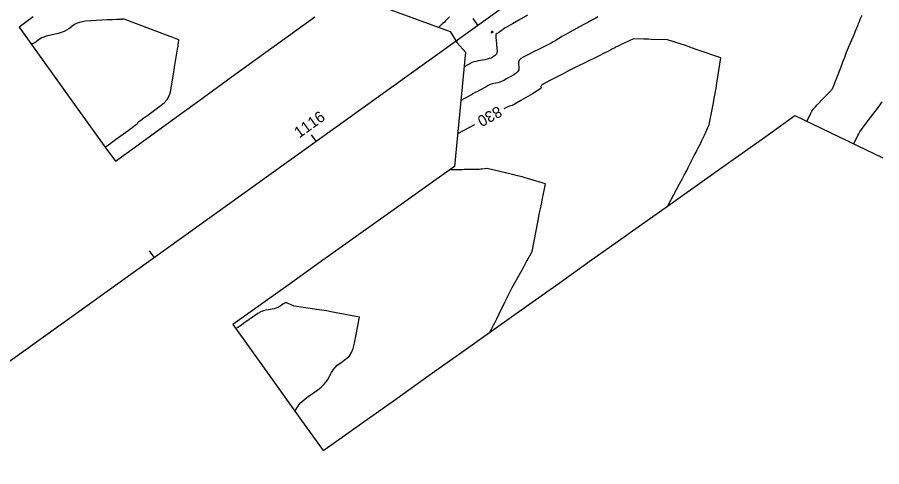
# Model space of a CAD drawing. Extents: x 2079879 to 2092887, y 778083 to 784051.
# Drawn here: x 2083587.5 to 2083804.7, y 780682.1 to 780794.9 of the extents above; entities that cross this region are included whole.
import ezdxf

# ---------------------------------------------------------------- set-up
doc = ezdxf.new("R2010")
doc.units = 0
for name, color, linetype in [('DT_X_Contour_Major', 7, 'Continuous'), ('DT_X_Contour_Minor', 7, 'Continuous'), ('DT_X_TIN_Hull', 7, 'Continuous'), ('GE_X_CL_20', 7, 'Continuous')]:
    doc.layers.add(name, color=color, linetype=linetype)

msp = doc.modelspace()

# ---------------------------------------------------------------- linework, layer by layer
at = {"layer": 'DT_X_Contour_Major'}
for points in [[(2083750.94, 780747.61), (2083753.91, 780753.14), (2083754.53, 780754.28), (2083755.09, 780755.35), (2083755.61, 780756.34), (2083756.08, 780757.25), (2083757.26, 780759.59), (2083757.68, 780760.41), (2083758.04, 780761.12), (2083758.35, 780761.72), (2083758.61, 780762.21), (2083759.21, 780763.39), (2083759.44, 780763.84), (2083759.68, 780764.33), (2083759.93, 780764.84), (2083760.18, 780765.39), (2083761.37, 780768), (2083762.4, 780773.44), (2083762.62, 780774.62), (2083762.84, 780775.86), (2083763.06, 780777.13), (2083763.28, 780778.45), (2083764.3, 780784.73), (2083758.33, 780786.8), (2083757.12, 780787.22), (2083756.05, 780787.59), (2083755.11, 780787.91), (2083754.3, 780788.17), (2083750.87, 780789.29), (2083746.79, 780789.41), (2083746.14, 780789.43), (2083745.52, 780789.45), (2083744.94, 780789.47), (2083742.35, 780789.55), (2083739.07, 780788.01), (2083738.45, 780787.71), (2083738, 780787.5), (2083737.72, 780787.37), (2083737.61, 780787.32), (2083736.93, 780786.95), (2083736.82, 780786.89), (2083736.73, 780786.84), (2083736.68, 780786.81), (2083736.64, 780786.79), (2083736.59, 780786.75), (2083736.4, 780786.65), (2083735.85, 780786.37), (2083734.95, 780785.93), (2083733.7, 780785.31), (2083729.91, 780783.42), (2083728.51, 780782.73), (2083727.17, 780782.06), (2083725.88, 780781.41), (2083724.65, 780780.79), (2083721.45, 780779.15), (2083720.4, 780778.6), (2083719.66, 780778.16), (2083719.21, 780777.84), (2083719.08, 780777.64), (2083719.12, 780777.26), (2083718.99, 780777.05), (2083718.59, 780776.73), (2083717.91, 780776.28), (2083716.96, 780775.72), (2083714.04, 780774.05), (2083713.06, 780773.49), (2083712.32, 780773.09), (2083711.82, 780772.84), (2083711.55, 780772.74), (2083711.16, 780772.66), (2083710.9, 780772.57), (2083710.43, 780772.34), (2083709.75, 780771.99), (2083709.74, 780771.98)], [(2083702.38, 780767.95), (2083702.37, 780767.94), (2083698.15, 780765.68)]]:
    msp.add_lwpolyline(points, dxfattribs=at)
at = {"layer": 'DT_X_Contour_Minor'}
for points in [[(2083609.68, 780762.3), (2083609.8, 780762.48), (2083609.97, 780762.62), (2083610.43, 780762.96), (2083611.18, 780763.5), (2083612.22, 780764.25), (2083615.37, 780766.52), (2083616.42, 780767.28), (2083617.17, 780767.84), (2083617.64, 780768.21), (2083617.82, 780768.38), (2083617.93, 780768.6), (2083618.11, 780768.77), (2083618.56, 780769.13), (2083619.3, 780769.68), (2083620.32, 780770.41), (2083623.39, 780772.63), (2083624.42, 780773.47), (2083625.2, 780774.35), (2083625.73, 780775.25), (2083626.01, 780776.19), (2083626.43, 780778.73), (2083626.59, 780779.7), (2083626.75, 780780.72), (2083626.93, 780781.79), (2083627.12, 780782.91), (2083627.62, 780785.94), (2083627.79, 780786.96), (2083627.92, 780787.73), (2083628, 780788.25), (2083628.05, 780788.53), (2083628.15, 780789.25), (2083627.43, 780789.56), (2083627.06, 780789.71), (2083626.24, 780790.03), (2083624.99, 780790.5), (2083623.29, 780791.14), (2083614.37, 780794.51), (2083613.88, 780794.45), (2083613.78, 780794.44), (2083613.69, 780794.44), (2083613.61, 780794.43), (2083613.53, 780794.43), (2083613.34, 780794.43), (2083613.08, 780794.42), (2083612.46, 780794.38), (2083611.48, 780794.34), (2083610.13, 780794.27), (2083606.06, 780794.06), (2083604.66, 780793.94), (2083603.5, 780793.74), (2083602.59, 780793.47), (2083601.93, 780793.11), (2083600.51, 780792.06), (2083599.93, 780791.7), (2083599.29, 780791.38), (2083598.58, 780791.12), (2083597.79, 780790.9), (2083595.6, 780790.4), (2083594.84, 780790.21), (2083594.2, 780790), (2083593.69, 780789.79), (2083593.31, 780789.56), (2083592.46, 780788.93), (2083592.17, 780788.72), (2083591.92, 780788.57), (2083591.72, 780788.46), (2083591.58, 780788.41), (2083591, 780788.29)], [(2083696.1, 780795.09), (2083695.64, 780794.6), (2083695.27, 780794.22), (2083695, 780793.94), (2083694.82, 780793.76), (2083694.47, 780793.43), (2083694.34, 780793.31), (2083694.21, 780793.19), (2083694.09, 780793.07), (2083693.97, 780792.96), (2083693.42, 780792.44)], [(2083733.38, 780795.03), (2083732.72, 780794.67), (2083732.34, 780794.47), (2083731.71, 780794.13), (2083730.83, 780793.64), (2083729.69, 780793.03), (2083726.32, 780791.19), (2083725.19, 780790.57), (2083724.33, 780790.09), (2083723.73, 780789.74), (2083723.39, 780789.53), (2083722.86, 780789.15), (2083722.59, 780788.98), (2083722.19, 780788.75), (2083721.65, 780788.47), (2083720.98, 780788.13), (2083719, 780787.15), (2083718.27, 780786.79), (2083717.58, 780786.44), (2083716.91, 780786.1), (2083716.27, 780785.78), (2083714.6, 780784.93), (2083714.06, 780784.59), (2083713.69, 780784.23), (2083713.48, 780783.83), (2083713.44, 780783.4), (2083713.57, 780782.21), (2083713.52, 780781.77), (2083713.29, 780781.34), (2083712.87, 780780.93), (2083712.27, 780780.52), (2083710.42, 780779.46), (2083709.76, 780779.11), (2083709.18, 780778.83), (2083708.68, 780778.64), (2083708.26, 780778.52), (2083707.24, 780778.33), (2083706.83, 780778.22), (2083706.37, 780778.06), (2083705.85, 780777.83), (2083705.29, 780777.53), (2083703.71, 780776.66), (2083703.13, 780776.34), (2083702.56, 780776.03), (2083702.01, 780775.72), (2083701.46, 780775.43), (2083698.98, 780774.1)], [(2083715.72, 780795.44), (2083713.56, 780794.26), (2083711.92, 780793.34), (2083710.78, 780792.67), (2083710.14, 780792.27), (2083709.13, 780791.55), (2083708.79, 780791.31), (2083708.53, 780791.13), (2083708.35, 780791.01), (2083708.25, 780790.95), (2083708.1, 780790.87), (2083708.04, 780790.84), (2083707.99, 780790.82), (2083707.93, 780790.79), (2083707.88, 780790.76), (2083707.76, 780790.7), (2083707.72, 780790.58), (2083707.72, 780790.29), (2083707.75, 780789.81), (2083707.81, 780789.15), (2083708.02, 780787.16), (2083708.05, 780786.49), (2083707.98, 780785.96), (2083707.83, 780785.57), (2083707.58, 780785.33), (2083706.8, 780784.88), (2083706.46, 780784.72), (2083706.05, 780784.57), (2083705.55, 780784.43), (2083704.97, 780784.31), (2083703.32, 780784), (2083702.76, 780783.88), (2083702.3, 780783.77), (2083701.96, 780783.67), (2083701.72, 780783.56), (2083701.24, 780783.3), (2083701.07, 780783.2), (2083700.89, 780783.11), (2083700.72, 780783.01), (2083700.56, 780782.93), (2083699.8, 780782.52)], [(2083785.88, 780768.82), (2083786.88, 780770.9), (2083787.14, 780771.36), (2083787.49, 780771.86), (2083787.93, 780772.4), (2083788.47, 780772.98), (2083790.02, 780774.57), (2083790.55, 780775.12), (2083790.98, 780775.56), (2083791.31, 780775.89), (2083791.53, 780776.12), (2083792.34, 780776.96), (2083794.46, 780782.55), (2083794.92, 780783.75), (2083795.4, 780784.95), (2083795.88, 780786.16), (2083796.38, 780787.37), (2083797.73, 780790.59), (2083798.18, 780791.68), (2083798.52, 780792.5), (2083798.76, 780793.07), (2083798.88, 780793.39), (2083799.08, 780793.89), (2083799.15, 780794.07), (2083799.23, 780794.26), (2083799.3, 780794.44), (2083799.38, 780794.63), (2083799.75, 780795.49)], [(2083706.89, 780791.1), (2083706.85, 780791.08), (2083706.82, 780791.06), (2083706.79, 780791.04), (2083706.76, 780791.02), (2083706.63, 780790.94), (2083706.67, 780791.01), (2083706.68, 780791.02), (2083706.68, 780791.05), (2083706.69, 780791.08), (2083706.7, 780791.12), (2083706.73, 780791.32), (2083706.74, 780791.38), (2083706.76, 780791.5), (2083706.81, 780791.5), (2083706.82, 780791.5), (2083706.84, 780791.48), (2083706.87, 780791.45), (2083706.9, 780791.41), (2083706.99, 780791.29), (2083707.02, 780791.25), (2083707.02, 780791.21), (2083707.01, 780791.18), (2083706.99, 780791.16), (2083706.89, 780791.1)], [(2083797.66, 780763.17), (2083798.65, 780765.24), (2083798.9, 780765.71), (2083799.21, 780766.22), (2083799.59, 780766.77), (2083800.02, 780767.37), (2083802.16, 780770.17), (2083803.84, 780772.38), (2083804.26, 780772.95), (2083804.81, 780773.76)], [(2083706.23, 780715.89), (2083706.68, 780716.7), (2083706.77, 780716.87), (2083706.86, 780717.02), (2083706.94, 780717.17), (2083707.01, 780717.3), (2083707.19, 780717.64), (2083707.32, 780717.91), (2083707.59, 780718.45), (2083707.98, 780719.25), (2083708.5, 780720.33), (2083710.06, 780723.58), (2083710.66, 780724.79), (2083711.26, 780725.97), (2083711.87, 780727.14), (2083712.5, 780728.29), (2083714.75, 780732.35), (2083715.18, 780733.12), (2083715.47, 780733.64), (2083715.63, 780733.92), (2083715.85, 780734.33), (2083715.94, 780734.49), (2083716.04, 780734.67), (2083716.16, 780734.87), (2083716.28, 780735.08), (2083716.87, 780736.13), (2083718.37, 780743.94), (2083718.68, 780745.51), (2083718.95, 780746.88), (2083719.19, 780748.06), (2083719.39, 780749.04), (2083720.25, 780753.14), (2083716.31, 780754.33), (2083715.4, 780754.59), (2083714.37, 780754.87), (2083713.2, 780755.17), (2083711.91, 780755.49), (2083705.58, 780756.99), (2083704.31, 780756.83), (2083703.99, 780756.79), (2083703.59, 780756.77), (2083703.1, 780756.75), (2083702.53, 780756.74), (2083700.88, 780756.72), (2083700.3, 780756.72), (2083699.77, 780756.71), (2083699.3, 780756.7), (2083698.89, 780756.69), (2083697.88, 780756.67), (2083697.54, 780756.66), (2083697.25, 780756.66), (2083697.02, 780756.65), (2083696.86, 780756.66), (2083696.23, 780756.68)], [(2083657.28, 780696.11), (2083658.39, 780697.77), (2083658.71, 780698.16), (2083659.19, 780698.63), (2083659.84, 780699.16), (2083660.65, 780699.76), (2083663.04, 780701.47), (2083663.86, 780702.11), (2083664.56, 780702.76), (2083665.12, 780703.41), (2083665.54, 780704.06), (2083666.5, 780705.81), (2083666.9, 780706.45), (2083667.38, 780707.04), (2083667.93, 780707.59), (2083668.56, 780708.09), (2083670.35, 780709.37), (2083670.97, 780709.96), (2083671.49, 780710.79), (2083671.92, 780711.84), (2083672.24, 780713.12), (2083673.53, 780719.64), (2083667.68, 780720.79), (2083666.43, 780721.02), (2083665.19, 780721.24), (2083663.97, 780721.45), (2083662.75, 780721.63), (2083657.08, 780722.45), (2083655.6, 780723.14), (2083655.27, 780723.24), (2083654.95, 780723.24), (2083654.61, 780723.15), (2083654.28, 780722.95), (2083653.37, 780722.31), (2083653, 780722.08), (2083652.57, 780721.9), (2083652.09, 780721.76), (2083651.55, 780721.66), (2083650.03, 780721.43), (2083649.42, 780721.28), (2083648.73, 780720.99), (2083647.96, 780720.56), (2083647.11, 780720), (2083644.72, 780718.3), (2083643.93, 780717.74), (2083643.34, 780717.33), (2083642.96, 780717.07), (2083642.77, 780716.96), (2083642.39, 780716.82)]]:
    msp.add_lwpolyline(points, dxfattribs=at)
at = {"layer": 'DT_X_TIN_Hull'}
for points in [[(2083670.35, 780800.92), (2083696.28, 780791.39), (2083698.05, 780788.51), (2083700.16, 780786.2), (2083697.34, 780757.47), (2083691.57, 780753.36), (2083683.43, 780747.56), (2083677.65, 780743.44), (2083669.51, 780737.64), (2083663.73, 780733.53), (2083655.59, 780727.73), (2083649.81, 780723.62), (2083641.67, 780717.82), (2083644.68, 780713.63), (2083651.65, 780703.94), (2083658.53, 780694.36), (2083664.42, 780686.18), (2083666.57, 780687.71), (2083674.72, 780693.5), (2083682.87, 780699.29), (2083691.02, 780705.08), (2083699.18, 780710.88), (2083707.33, 780716.66), (2083715.48, 780722.45), (2083723.64, 780728.24), (2083731.79, 780734.03), (2083739.95, 780739.82), (2083742.1, 780741.34), (2083750.25, 780747.13), (2083758.41, 780752.91), (2083766.57, 780758.69), (2083774.73, 780764.48), (2083782.89, 780770.26), (2083804.98, 780759.65)], [(2083591.54, 780795.05), (2083588, 780792.45), (2083596.01, 780781.31), (2083603.2, 780771.31), (2083609.81, 780762.13), (2083612.2, 780758.81), (2083616.97, 780762.28), (2083625.06, 780768.15), (2083633.16, 780774.02), (2083641.26, 780779.89), (2083649.36, 780785.75), (2083654.14, 780789.21), (2083662.25, 780795.07)]]:
    msp.add_lwpolyline(points, dxfattribs=at)
at = {"layer": 'GE_X_CL_20'}
for p, q in [((2079923.52, 778084.44), (2085691.45, 782217.74)), ((2083703.24, 780792.98), (2083702.07, 780794.61)), ((2083662.6, 780763.86), (2083661.43, 780765.48)), ((2083621.95, 780734.73), (2083620.79, 780736.36))]:
    msp.add_line(p, q, dxfattribs=at)

# ---------------------------------------------------------------- texts
at = {"layer": 'DT_X_Contour_Major'}
msp.add_text('830', height=2.8, rotation=208.7254, dxfattribs=at).set_placement((2083708.31, 780772.78))
at = {"layer": 'GE_X_CL_20'}
msp.add_text('1116', height=2.8, rotation=35.6254, dxfattribs=at).set_placement((2083658.36, 780764.51))

doc.saveas('drawing.dxf')
